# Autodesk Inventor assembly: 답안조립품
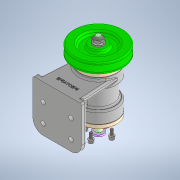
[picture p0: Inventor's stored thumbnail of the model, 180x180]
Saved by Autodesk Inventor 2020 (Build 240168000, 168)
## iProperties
Created: 2024-02
Part Number: 답안조립품
Document SubType Name: Assembly
Designer: oem
Author: oem
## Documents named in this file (18)
- C:\Users\oem\Desktop\740204V1008\답안조립품.iam
- C:\Users\oem\Desktop\740204V1008\육각 소켓 머리 볼트 M4 x 10.ipt
- C:\Users\oem\Desktop\740204V1008\육각 소켓 머리 볼트 M5 x 12.ipt
- C:\Users\oem\Desktop\740204V1008\축.ipt
- C:\Users\oem\Desktop\740204V1008\커버.ipt
- C:\Users\oem\Desktop\740204V1008\평와셔 M10.ipt
- C:\Users\oem\Desktop\740204V1008\평행 키 5x5x12.ipt
- C:\Users\oem\Desktop\740204V1008\플랜지.ipt
- C:\Users\oem\Desktop\740204V1008\V-벨트풀리.ipt
- C:\Users\oem\Desktop\740204V1008\가스켓.ipt
- C:\Users\oem\Desktop\740204V1008\깊은 홈 볼 베어링 6204.ipt
- C:\Users\oem\Desktop\740204V1008\본체.ipt
- C:\Users\oem\Desktop\740204V1008\스프로킷.ipt
- C:\Users\oem\Desktop\740204V1008\스프링 와셔 M5.ipt
- C:\Users\oem\Desktop\740204V1008\스프링 와셔 M10.ipt
- C:\Users\oem\Desktop\740204V1008\앤드 캡.ipt
- C:\Users\oem\Desktop\740204V1008\오일 실 20 32 5.ipt
- C:\Users\oem\Desktop\740204V1008\육각 너트 M10x1.ipt
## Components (4 placed, 3 different names)
1. 플랜지:1
2. V-벨트풀리:1 — 각도:1, 각도:2
3. 가스켓:1
4. 가스켓:2
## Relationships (2: Angle 2)
- 각도:1 [Angle]: V-벨트풀리:1
- 각도:2 [Angle]: V-벨트풀리:1
